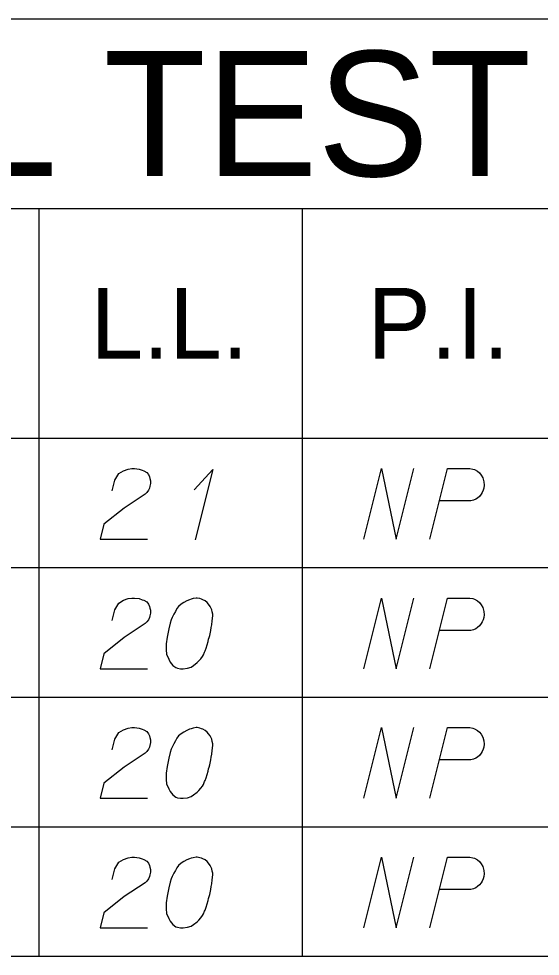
# Model space of a CAD drawing. Extents: x 2074207 to 2076812, y 516372 to 523312.
# Drawn here: x 2076488.9 to 2076524.4, y 516865.7 to 516929.4 of the extents above; entities that cross this region are included whole.
import ezdxf

# ---------------------------------------------------------------- set-up
doc = ezdxf.new("R2010")
doc.units = 0
for name, color, linetype in [('Prop DirtTable_ Soil Test Results - Outline (Major)', 7, 'Continuous'), ('Prop DirtTable_ Soil Test Results - Outline (Minor)', 7, 'Continuous'), ('Prop DirtTable_ Soil Test Results - Tx (Header - Large)', 7, 'Continuous'), ('Prop DirtTable_ Soil Test Results - Tx (Header - Small)', 7, 'Continuous'), ('Prop DirtTable_ Soil Test Results - Tx (Sample Data)', 7, 'Continuous')]:
    doc.layers.add(name, color=color, linetype=linetype)

msp = doc.modelspace()

# ---------------------------------------------------------------- linework, layer by layer
at = {"layer": 'Prop DirtTable_ Soil Test Results - Outline (Major)'}
for p, q in [((2076260.609, 516929.359), (2076811.903, 516929.359)), ((2076260.609, 516900.874), (2076811.903, 516900.874)), ((2076260.609, 516900.874), (2076811.903, 516900.874)), ((2076260.609, 516865.674), (2076811.903, 516865.674))]:
    msp.add_line(p, q, dxfattribs=at)
at = {"layer": 'Prop DirtTable_ Soil Test Results - Outline (Minor)'}
for p, q in [((2076260.609, 516916.474), (2076811.903, 516916.474)), ((2076490.31, 516916.474), (2076490.31, 516892.074)), ((2076508.192, 516916.474), (2076508.192, 516892.074)), ((2076260.609, 516892.074), (2076811.903, 516892.074)), ((2076260.609, 516892.074), (2076811.903, 516892.074)), ((2076490.31, 516892.074), (2076490.31, 516883.274)), ((2076508.192, 516892.074), (2076508.192, 516883.274)), ((2076260.609, 516883.274), (2076811.903, 516883.274)), ((2076260.609, 516883.274), (2076811.903, 516883.274)), ((2076490.31, 516883.274), (2076490.31, 516874.474)), ((2076508.192, 516883.274), (2076508.192, 516874.474)), ((2076260.609, 516874.474), (2076811.903, 516874.474)), ((2076260.609, 516874.474), (2076811.903, 516874.474)), ((2076490.31, 516874.474), (2076490.31, 516865.674)), ((2076508.192, 516874.474), (2076508.192, 516865.674)), ((2076260.609, 516865.674), (2076811.903, 516865.674))]:
    msp.add_line(p, q, dxfattribs=at)
at = {"layer": 'Prop DirtTable_ Soil Test Results - Tx (Sample Data)'}
for points in [[(2076495.287, 516897.293), (2076495.463, 516898.011), (2076495.746, 516898.465), (2076496.063, 516898.654), (2076496.38, 516898.767), (2076496.627, 516898.805), (2076496.804, 516898.805), (2076497.121, 516898.767), (2076497.333, 516898.692), (2076497.439, 516898.654), (2076497.65, 516898.541), (2076497.756, 516898.389), (2076497.827, 516898.238), (2076497.862, 516898.125), (2076497.897, 516897.974), (2076497.897, 516897.785), (2076497.862, 516897.596), (2076497.827, 516897.482), (2076497.756, 516897.331), (2076497.65, 516897.18), (2076497.545, 516897.067), (2076496.098, 516896.122), (2076494.723, 516895.026), (2076494.476, 516894.005), (2076497.686, 516894.005)], [(2076500.86, 516897.369), (2076502.13, 516898.73), (2076500.931, 516893.967)], [(2076512.396, 516894.005), (2076513.595, 516898.805), (2076514.583, 516894.005), (2076515.782, 516898.805)], [(2076516.876, 516894.005), (2076518.075, 516898.805), (2076519.592, 516898.805), (2076519.803, 516898.767), (2076519.909, 516898.73), (2076520.121, 516898.616), (2076520.262, 516898.503), (2076520.368, 516898.352), (2076520.474, 516898.163), (2076520.544, 516897.898), (2076520.58, 516897.671), (2076520.544, 516897.482), (2076520.509, 516897.331), (2076520.438, 516897.18), (2076520.368, 516897.067), (2076520.262, 516896.915), (2076520.121, 516896.802), (2076520.015, 516896.726), (2076519.839, 516896.651), (2076519.662, 516896.613), (2076517.546, 516896.613)], [(2076495.287, 516888.493), (2076495.463, 516889.211), (2076495.746, 516889.665), (2076496.063, 516889.854), (2076496.38, 516889.967), (2076496.627, 516890.005), (2076496.804, 516890.005), (2076497.121, 516889.967), (2076497.333, 516889.892), (2076497.439, 516889.854), (2076497.65, 516889.741), (2076497.756, 516889.589), (2076497.827, 516889.438), (2076497.862, 516889.325), (2076497.897, 516889.174), (2076497.897, 516888.985), (2076497.862, 516888.796), (2076497.827, 516888.682), (2076497.756, 516888.531), (2076497.65, 516888.38), (2076497.545, 516888.267), (2076496.098, 516887.322), (2076494.723, 516886.226), (2076494.476, 516885.205), (2076497.686, 516885.205)], [(2076501.072, 516890.005), (2076501.002, 516890.005), (2076500.79, 516889.967), (2076500.649, 516889.93), (2076500.543, 516889.892), (2076500.367, 516889.816), (2076500.155, 516889.703), (2076499.979, 516889.589), (2076499.802, 516889.438), (2076499.696, 516889.287), (2076499.591, 516889.098), (2076499.485, 516888.909), (2076499.379, 516888.682), (2076499.308, 516888.531), (2076499.238, 516888.304), (2076499.132, 516887.926), (2076499.026, 516887.359), (2076498.956, 516886.906), (2076498.956, 516886.49), (2076498.991, 516886.188), (2076499.132, 516885.848), (2076499.238, 516885.659), (2076499.414, 516885.432), (2076499.626, 516885.281), (2076499.732, 516885.243), (2076499.943, 516885.205), (2076500.12, 516885.205), (2076500.402, 516885.243), (2076500.649, 516885.319), (2076500.825, 516885.432), (2076501.072, 516885.621), (2076501.178, 516885.734), (2076501.319, 516885.885), (2076501.425, 516886.037), (2076501.495, 516886.15), (2076501.566, 516886.339), (2076501.601, 516886.415), (2076501.672, 516886.604), (2076501.742, 516886.83), (2076501.813, 516887.057), (2076501.848, 516887.208), (2076501.883, 516887.322), (2076501.919, 516887.473), (2076501.989, 516887.813), (2076502.025, 516888.002), (2076502.06, 516888.191), (2076502.095, 516888.456), (2076502.13, 516888.796), (2076502.13, 516888.909), (2076502.095, 516889.06), (2076502.06, 516889.211), (2076501.954, 516889.438), (2076501.848, 516889.589), (2076501.742, 516889.703), (2076501.601, 516889.816), (2076501.46, 516889.892), (2076501.354, 516889.93), (2076501.249, 516889.967), (2076501.072, 516890.005)], [(2076512.396, 516885.205), (2076513.595, 516890.005), (2076514.583, 516885.205), (2076515.782, 516890.005)], [(2076516.876, 516885.205), (2076518.075, 516890.005), (2076519.592, 516890.005), (2076519.803, 516889.967), (2076519.909, 516889.93), (2076520.121, 516889.816), (2076520.262, 516889.703), (2076520.368, 516889.552), (2076520.474, 516889.363), (2076520.544, 516889.098), (2076520.58, 516888.871), (2076520.544, 516888.682), (2076520.509, 516888.531), (2076520.438, 516888.38), (2076520.368, 516888.267), (2076520.262, 516888.115), (2076520.121, 516888.002), (2076520.015, 516887.926), (2076519.839, 516887.851), (2076519.662, 516887.813), (2076517.546, 516887.813)], [(2076495.287, 516879.693), (2076495.463, 516880.411), (2076495.746, 516880.865), (2076496.063, 516881.054), (2076496.38, 516881.167), (2076496.627, 516881.205), (2076496.804, 516881.205), (2076497.121, 516881.167), (2076497.333, 516881.092), (2076497.439, 516881.054), (2076497.65, 516880.941), (2076497.756, 516880.789), (2076497.827, 516880.638), (2076497.862, 516880.525), (2076497.897, 516880.374), (2076497.897, 516880.185), (2076497.862, 516879.996), (2076497.827, 516879.882), (2076497.756, 516879.731), (2076497.65, 516879.58), (2076497.545, 516879.467), (2076496.098, 516878.522), (2076494.723, 516877.426), (2076494.476, 516876.405), (2076497.686, 516876.405)], [(2076501.072, 516881.205), (2076501.002, 516881.205), (2076500.79, 516881.167), (2076500.649, 516881.13), (2076500.543, 516881.092), (2076500.367, 516881.016), (2076500.155, 516880.903), (2076499.979, 516880.789), (2076499.802, 516880.638), (2076499.696, 516880.487), (2076499.591, 516880.298), (2076499.485, 516880.109), (2076499.379, 516879.882), (2076499.308, 516879.731), (2076499.238, 516879.504), (2076499.132, 516879.126), (2076499.026, 516878.559), (2076498.956, 516878.106), (2076498.956, 516877.69), (2076498.991, 516877.388), (2076499.132, 516877.048), (2076499.238, 516876.859), (2076499.414, 516876.632), (2076499.626, 516876.481), (2076499.732, 516876.443), (2076499.943, 516876.405), (2076500.12, 516876.405), (2076500.402, 516876.443), (2076500.649, 516876.519), (2076500.825, 516876.632), (2076501.072, 516876.821), (2076501.178, 516876.934), (2076501.319, 516877.085), (2076501.425, 516877.237), (2076501.495, 516877.35), (2076501.566, 516877.539), (2076501.601, 516877.615), (2076501.672, 516877.804), (2076501.742, 516878.03), (2076501.813, 516878.257), (2076501.848, 516878.408), (2076501.883, 516878.522), (2076501.919, 516878.673), (2076501.989, 516879.013), (2076502.025, 516879.202), (2076502.06, 516879.391), (2076502.095, 516879.656), (2076502.13, 516879.996), (2076502.13, 516880.109), (2076502.095, 516880.26), (2076502.06, 516880.411), (2076501.954, 516880.638), (2076501.848, 516880.789), (2076501.742, 516880.903), (2076501.601, 516881.016), (2076501.46, 516881.092), (2076501.354, 516881.13), (2076501.249, 516881.167), (2076501.072, 516881.205)], [(2076512.396, 516876.405), (2076513.595, 516881.205), (2076514.583, 516876.405), (2076515.782, 516881.205)], [(2076516.876, 516876.405), (2076518.075, 516881.205), (2076519.592, 516881.205), (2076519.803, 516881.167), (2076519.909, 516881.13), (2076520.121, 516881.016), (2076520.262, 516880.903), (2076520.368, 516880.752), (2076520.474, 516880.563), (2076520.544, 516880.298), (2076520.58, 516880.071), (2076520.544, 516879.882), (2076520.509, 516879.731), (2076520.438, 516879.58), (2076520.368, 516879.467), (2076520.262, 516879.315), (2076520.121, 516879.202), (2076520.015, 516879.126), (2076519.839, 516879.051), (2076519.662, 516879.013), (2076517.546, 516879.013)], [(2076495.287, 516870.893), (2076495.463, 516871.611), (2076495.746, 516872.065), (2076496.063, 516872.254), (2076496.38, 516872.367), (2076496.627, 516872.405), (2076496.804, 516872.405), (2076497.121, 516872.367), (2076497.333, 516872.292), (2076497.439, 516872.254), (2076497.65, 516872.141), (2076497.756, 516871.989), (2076497.827, 516871.838), (2076497.862, 516871.725), (2076497.897, 516871.574), (2076497.897, 516871.385), (2076497.862, 516871.196), (2076497.827, 516871.082), (2076497.756, 516870.931), (2076497.65, 516870.78), (2076497.545, 516870.667), (2076496.098, 516869.722), (2076494.723, 516868.626), (2076494.476, 516867.605), (2076497.686, 516867.605)], [(2076501.072, 516872.405), (2076501.002, 516872.405), (2076500.79, 516872.367), (2076500.649, 516872.33), (2076500.543, 516872.292), (2076500.367, 516872.216), (2076500.155, 516872.103), (2076499.979, 516871.989), (2076499.802, 516871.838), (2076499.696, 516871.687), (2076499.591, 516871.498), (2076499.485, 516871.309), (2076499.379, 516871.082), (2076499.308, 516870.931), (2076499.238, 516870.704), (2076499.132, 516870.326), (2076499.026, 516869.759), (2076498.956, 516869.306), (2076498.956, 516868.89), (2076498.991, 516868.588), (2076499.132, 516868.248), (2076499.238, 516868.059), (2076499.414, 516867.832), (2076499.626, 516867.681), (2076499.732, 516867.643), (2076499.943, 516867.605), (2076500.12, 516867.605), (2076500.402, 516867.643), (2076500.649, 516867.719), (2076500.825, 516867.832), (2076501.072, 516868.021), (2076501.178, 516868.134), (2076501.319, 516868.285), (2076501.425, 516868.437), (2076501.495, 516868.55), (2076501.566, 516868.739), (2076501.601, 516868.815), (2076501.672, 516869.004), (2076501.742, 516869.23), (2076501.813, 516869.457), (2076501.848, 516869.608), (2076501.883, 516869.722), (2076501.919, 516869.873), (2076501.989, 516870.213), (2076502.025, 516870.402), (2076502.06, 516870.591), (2076502.095, 516870.856), (2076502.13, 516871.196), (2076502.13, 516871.309), (2076502.095, 516871.46), (2076502.06, 516871.611), (2076501.954, 516871.838), (2076501.848, 516871.989), (2076501.742, 516872.103), (2076501.601, 516872.216), (2076501.46, 516872.292), (2076501.354, 516872.33), (2076501.249, 516872.367), (2076501.072, 516872.405)], [(2076512.396, 516867.605), (2076513.595, 516872.405), (2076514.583, 516867.605), (2076515.782, 516872.405)], [(2076516.876, 516867.605), (2076518.075, 516872.405), (2076519.592, 516872.405), (2076519.803, 516872.367), (2076519.909, 516872.33), (2076520.121, 516872.216), (2076520.262, 516872.103), (2076520.368, 516871.952), (2076520.474, 516871.763), (2076520.544, 516871.498), (2076520.58, 516871.271), (2076520.544, 516871.082), (2076520.509, 516870.931), (2076520.438, 516870.78), (2076520.368, 516870.667), (2076520.262, 516870.515), (2076520.121, 516870.402), (2076520.015, 516870.326), (2076519.839, 516870.251), (2076519.662, 516870.213), (2076517.546, 516870.213)]]:
    msp.add_lwpolyline(points, dxfattribs=at)

# ---------------------------------------------------------------- texts
at = {"layer": 'Prop DirtTable_ Soil Test Results - Tx (Header - Large)'}
msp.add_text('SOIL TEST RESULTS', height=8.50001, dxfattribs=at).set_placement((2076465.656, 516918.667))
at = {"layer": 'Prop DirtTable_ Soil Test Results - Tx (Header - Small)'}
for s, p in [('L.L.', (2076493.827, 516906.274)), ('P.I.', (2076512.654, 516906.274))]:
    msp.add_text(s, height=4.8, dxfattribs=at).set_placement(p)

doc.saveas('drawing.dxf')
